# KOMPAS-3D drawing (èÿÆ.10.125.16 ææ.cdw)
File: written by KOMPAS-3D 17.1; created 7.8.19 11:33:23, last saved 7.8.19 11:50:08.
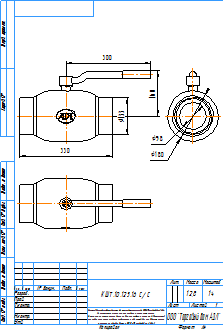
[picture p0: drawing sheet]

Sheet 1: A4, portrait

Title block, sheet 1: name: КШТ.10.125.16 С/С; material: Сталь 20  ГОСТ 1050-2013; mass: 12,8; sheets: 1; sheet format: A4; stored path: C:\Users\kka\KOMPAS_Work\Модели кранов для исследований\DN125\КШТ.10.125.16 СС.cdw

Views: Вид 1, Проекционный вид 2, Проекционный вид 3
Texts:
  kka
  adl
  Рама для чертежей
  Лит-Масса-Масштаб
  Материал-Предприятие
  Масштаб
  Изм.
  Лист
  № докум.
  Подп.
  Дата
  Лит.
  Разраб.
  Пров.
  Т.контр.
  Листов
  Внимание! Данный продукт является объектом авторского права ООО «Торговый Дом АДЛ».
  Запрещается изменение, копирование, распространение
  (в том числе путем копирования на другие сайты и ресурсы в Интернете)
  или любое иное использование информации и объектов без предварительного
  согласия правообладателя (ООО «Торговый Дом АДЛ»).
  Н.контр.
  Утв.
  ООО "Торговый дом АДЛ"
  Изменение
  Номер документа
  Подпись
  Обозначение документа
  Наименование изделия
  Масса изделия по ГОСТ 2.109-73
  Порядковый номер листа
  Общее количество листов в документе
  Характер работы, выполненной лицом, подписавшим документ
  Наименование или индекс предприятия, выпускающего документ
  Инв. № подл.
  Подп. и дата
  Взам. инв. №
  Инв. № дубл.
  Инвентарный номер подлинника по ГОСТ 2.501-68
  Подпись принявшего подлинник в отдел технической документации
  Инвентарный номер подлинника, взамен которого выпущен данный подлинник
  Инвентарный номер дубликата по ГОСТ 2.502-68
  Подпись принявшего дубликат в отдел технической документации
  Справ. №
  Перв. примен.
  Обозначение документа, взамен или на основании которого выпущен данный документ
  Обозначение документа, в котором впервые записан данный документ
  Подпись лица, копировавшего чертеж
  Обозначение формата листа
  !Рама для чертежа
Dimensions and other numbers on the sheet: 300; 330; 133; 160; 98; 180; 1:4; 1; 12,8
